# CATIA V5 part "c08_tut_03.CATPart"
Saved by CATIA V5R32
Part number: Boolean
Bounding box of the stored display mesh (mm): x -54.918 to 54.918, y -54.918 to 54.918, z -5 to 100
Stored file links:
  D:\PROJECTS\Project 2022\CATIA V5 6R 2022\Resources\Tutorial Files\c08_catia_v5_6r2022_tut\c08_tut_03.CATPart
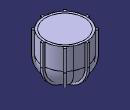
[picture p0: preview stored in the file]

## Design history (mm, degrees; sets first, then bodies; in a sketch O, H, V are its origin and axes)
Body1 (main body)
Body2 "Result"
  Body3 "Material_addition"
    Body4 "Base_feature"
      Solid1: linked copy from another document
    Add1: tool Body4
    Body5 "Rib"
      Solid2: linked copy from another document
      Thickness1: Thickness 1
      Body6 "Rib_plates"
        Sketch1 on face of Solid2, origin (0, 0, 100), H (1, 0, 0), V (0, 1, 0)
          line L1 (0, 0) -> (0, 73.1213)
          vertical: L1 V
        Pad1: profile Sketch1, direction (0, 0, 1), length 20, opposite side length 125, thin wall 6
        CircPattern1: of Pad1, instances 8, angular step 45 {= 360.0*1 deg/CircPattern1.AngularNumber}, axis from Z axis
      Intersect1: tool Body6
    Add2: tool Body5
  Add3: tool Body3
  Body7 "Material_removal"
    Body8 "core"
      Solid3: linked copy from another document
      Thickness2: Thickness 1
    Add4: tool Body8
  Remove1: tool Body7
Body9 "Base_feature"
  Sketch2 on yz-plane, origin (0, 0, 0), H (0, 1, 0), V (0, 0, 1)
    line L1 (0, 0) -> (0, 100)
    line L2 (0, 100) -> (50, 100)
    line L3 (50, 100) -> (50, 50)
    arc A1 centre (0, 50) radius 50 from (50, 50) to (0, 0) cw
    axis line L4 (0, 116.7367) -> (0, -14.1151)
    point P5 (0, 116.7367)
    point P6 (0, -14.1151)
    length L1 = 100
    length L2 = 50
    vertical: L1 V, L3 V, L4 V
    horizontal: L2 H
    tangency: A1 L3, A1 H
    coincidence: P5 V, P5 L1, P6 V
  Shaft1: profile Sketch2, axis Sketch2.L1, angle 360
